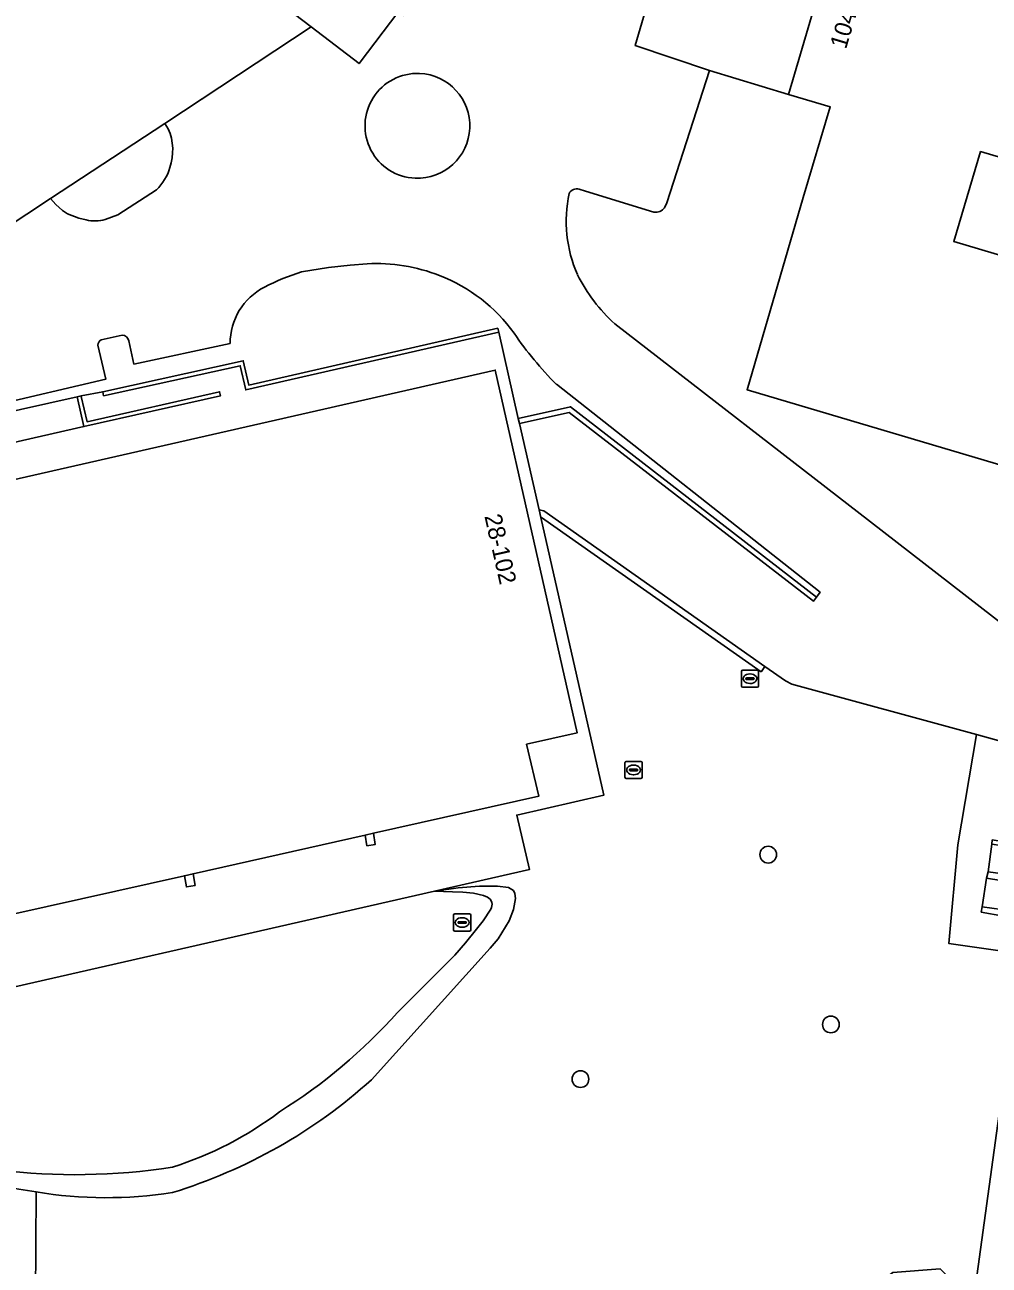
# Model space of a CAD drawing. Extents: x 161139 to 161601, y 381708 to 382245.
# Drawn here: x 161352.2 to 161408.5, y 381790 to 381862.4 of the extents above; entities that cross this region are included whole.
import ezdxf

# ---------------------------------------------------------------- set-up
doc = ezdxf.new("R2010")
doc.units = 0
for name, color, linetype in [('IMGEO_Boom', 7, 'Continuous'), ('IMGEO_Erf', 7, 'Continuous'), ('IMGEO_Groenvoorziening', 7, 'Continuous'), ('IMGEO_Hek', 7, 'Continuous'), ('IMGEO_Kolk', 7, 'Continuous'), ('IMGEO_Meer_plas_ven_vijver', 7, 'Continuous'), ('IMGEO_Muur', 7, 'Continuous'), ('IMGEO_Oever', 7, 'Continuous'), ('IMGEO_Pand', 7, 'Continuous'), ('IMGEO_Pand_nummerreeks', 7, 'Continuous'), ('IMGEO_Rijbaan_lokaal_open', 7, 'Continuous'), ('IMGEO_Rioolput', 7, 'Continuous'), ('IMGEO_Terreindeel_open', 7, 'Continuous'), ('IMGEO_Voetpad_gesloten', 7, 'Continuous'), ('IMGEO_Voetpad_op_trap', 7, 'Continuous'), ('IMGEO_Voetpad_open', 7, 'Continuous')]:
    doc.layers.add(name, color=color, linetype=linetype)

msp = doc.modelspace()

# ---------------------------------------------------------------- linework, layer by layer
at = {"layer": 'IMGEO_Boom'}
for centre in [(161395.64, 381813.956), (161399.298, 381804.049), (161384.68, 381800.857)]:
    msp.add_circle(centre, 0.489, dxfattribs=at)
at = {"layer": 'IMGEO_Erf'}
msp.add_lwpolyline([(161414.917, 381852.938), (161408.039, 381854.979), (161406.469, 381849.737), (161413.344, 381847.686)], close=True, dxfattribs=at)
at = {"layer": 'IMGEO_Groenvoorziening'}
for points in [[(161425.633, 381884.432), (161423.964, 381885.944), (161411.648, 381895.891), (161396.286, 381876.416), (161398.229, 381877.051), (161404.489, 381875.181), (161404.584, 381875.499), (161407.805, 381886.188), (161423.433, 381881.545), (161420.059, 381870.284), (161418.513, 381865.051), (161414.917, 381852.938), (161413.344, 381847.686), (161410.014, 381836.444), (161394.402, 381841.083), (161397.689, 381852.301)], [(161386.683, 381844.924), (161401.607, 381833.38), (161412.69, 381824.806), (161412.791, 381825.538), (161413.572, 381829.44), (161414.563, 381833.406), (161415.08, 381835.254), (161418.761, 381848.098), (161423.407, 381863.627), (161427.931, 381878.454)], [(161397.689, 381852.301), (161399.261, 381857.59), (161396.815, 381858.319), (161392.214, 381859.719), (161389.721, 381851.996), (161389.585, 381851.709)], [(161360.621, 381856.311), (161360.411, 381856.63), (161353.743, 381852.245), (161354.063, 381851.891), (161354.446, 381851.539), (161354.733, 381851.345), (161355.394, 381851.106), (161355.831, 381851.002)], [(161356.943, 381851.025), (161357.679, 381851.295), (161359.926, 381852.758)], [(161388.968, 381851.452), (161384.984, 381852.674), (161384.605, 381852.799)], [(161372.222, 381848.435), (161371.243, 381848.361), (161369.966, 381848.223), (161368.405, 381847.968)], [(161335.133, 381818.678), (161332.909, 381828.491), (161331.707, 381833.726), (161350.437, 381838.001), (161350.1, 381839.503), (161350.325, 381839.554), (161355.298, 381840.668), (161355.532, 381840.722), (161356.795, 381840.965), (161365.001, 381842.775), (161365.321, 381841.358), (161379.855, 381844.678), (161379.908, 381844.444), (161381.05, 381839.415), (161384.098, 381840.089), (161398.457, 381828.977), (161398.664, 381829.267), (161383.28, 381841.401)], [(161357.923, 381844.272), (161356.707, 381843.999)], [(161364.233, 381843.777), (161358.619, 381842.581), (161358.322, 381843.944)], [(161356.517, 381843.681), (161356.981, 381841.703), (161350.317, 381840.141), (161350.04, 381840.078), (161349.286, 381843.739)], [(161410.408, 381808.171), (161406.189, 381808.766), (161406.705, 381814.537), (161407.802, 381820.973), (161397.014, 381823.913), (161396.647, 381824.098), (161395.435, 381824.931), (161395.242, 381824.651), (161395.226, 381824.628), (161382.405, 381833.633), (161382.364, 381833.625), (161386.044, 381817.417), (161380.963, 381816.263), (161381.7, 381813.086), (161376.161, 381811.825), (161377.551, 381812.02), (161378.796, 381812.12), (161379.845, 381812.117), (161380.477, 381812.037), (161380.763, 381811.871), (161380.856, 381811.693), (161380.886, 381811.397), (161380.763, 381810.757), (161380.51, 381810.087), (161379.868, 381809.041), (161379.417, 381808.492), (161372.483, 381800.819)], [(161352.902, 381794.275), (161352.825, 381781.983), (161357.945, 381781.864), (161362.808, 381780.906), (161365.105, 381780.107), (161367.857, 381779.085), (161370.556, 381777.81), (161377.164, 381776.424), (161379.728, 381774.456), (161382.618, 381773.534), (161385.797, 381774.301), (161388.15, 381776.267), (161392.662, 381781.141), (161395.111, 381783.456), (161399.179, 381786.753), (161402.921, 381789.58), (161405.67, 381789.788), (161407.613, 381787.806), (161410.408, 381808.171)], [(161352.902, 381794.275), (161351.892, 381794.443), (161351.035, 381794.598), (161350.384, 381782.823), (161348.989, 381781.041), (161340.831, 381779.23), (161332.916, 381777.135), (161331.862, 381776.416), (161333.447, 381775.88), (161346.726, 381771.17)], [(161352.825, 381781.983), (161352.902, 381794.275)]]:
    msp.add_lwpolyline(points, dxfattribs=at)
msp.add_lwpolyline([(161411.998, 381819.791), (161407.802, 381820.973), (161406.705, 381814.537), (161406.189, 381808.766), (161410.408, 381808.171), (161410.678, 381810.137), (161408.076, 381810.606), (161408.129, 381810.903), (161408.388, 381812.589), (161408.472, 381812.962), (161408.693, 381814.567), (161408.72, 381814.815), (161411.254, 381814.406)], close=True, dxfattribs=at)
for centre, radius, start, end in [((161375.162, 381856.484), 3.059, 87.58326, 267.60119), ((161375.162, 381856.484), 3.059, 267.60197, 87.58247), ((161357.721, 381855.058), 3.159, 341.44108, 23.37512), ((161357.929, 381854.865), 2.904, 313.4615, 343.72954), ((161384.495, 381852.257), 0.553, 78.58059, 149.68807), ((161391.713, 381850.93), 7.861, 168.20877, 203.46151), ((161389.082, 381852.047), 0.606, 259.16034, 326.0662), ((161356.348, 381852.92), 1.986, 254.92393, 287.44588), ((161372.754, 381838.294), 10.155, 68.61842, 93.00158), ((161372.521, 381834.897), 13.704, 107.47696, 117.32043), ((161372.963, 381838.739), 9.665, 35.73286, 68.81125), ((161393.728, 381852.531), 10.368, 207.15062, 227.19873), ((161367.924, 381843.792), 3.691, 117.29862, 180.23837), ((161356.841, 381843.703), 0.325, 114.34721, 183.93748), ((161357.907, 381843.846), 0.426, 13.29849, 87.85734), ((161397.881, 381856.02), 20.662, 214.27938, 225.03631), ((161351.855, 381823.701), 30.808, 287.00415, 312.03533), ((161356.991, 381818.761), 24.825, 260.51996, 278.97631)]:
    msp.add_arc(centre, radius, start, end, dxfattribs=at)
at = {"layer": 'IMGEO_Hek'}
msp.add_lwpolyline([(161360.471, 381856.669), (161368.964, 381862.254)], dxfattribs=at)
at = {"layer": 'IMGEO_Kolk'}
for p, q in [((161377.275, 381809.571), (161377.275, 381810.423)), ((161377.35, 381810.497), (161378.202, 381810.497)), ((161377.534, 381809.991), (161377.534, 381810.003)), ((161377.972, 381809.954), (161377.574, 381809.954)), ((161377.577, 381810.04), (161377.975, 381810.04)), ((161377.763, 381810.277), (161377.788, 381810.277)), ((161378.018, 381810.003), (161378.018, 381809.991)), ((161378.276, 381810.423), (161378.276, 381809.571)), ((161378.202, 381809.497), (161377.35, 381809.497)), ((161377.786, 381809.717), (161377.761, 381809.717))]:
    msp.add_line(p, q, dxfattribs=at)
for points in [[(161377.275, 381809.571), (161377.275, 381810.423)], [(161377.35, 381810.497), (161378.202, 381810.497)], [(161378.276, 381810.423), (161378.276, 381809.571)], [(161378.202, 381809.497), (161377.35, 381809.497)]]:
    msp.add_lwpolyline(points, dxfattribs=at)
for centre, radius, start, end in [((161377.352, 381810.421), 0.0765, 91.55205, 178.44795), ((161377.352, 381810.421), 0.0765, 91.55205, 178.44795), ((161377.574, 381810), 0.0403, 85.87752, 175.75265), ((161377.571, 381809.99), 0.0366, 178.93798, 274.71019), ((161377.975, 381809.997), 0.043, 264.86636, 352.45326), ((161377.979, 381810.002), 0.0386, 1.73085, 96.63898), ((161378.2, 381810.421), 0.0765, 1.55205, 88.44795), ((161378.2, 381810.421), 0.0765, 1.55205, 88.44795), ((161377.352, 381809.573), 0.0765, 181.55205, 268.44795), ((161377.352, 381809.573), 0.0765, 181.55205, 268.44795), ((161378.2, 381809.573), 0.0765, 271.55205, 358.44795), ((161378.2, 381809.573), 0.0765, 271.55205, 358.44795)]:
    msp.add_arc(centre, radius, start, end, dxfattribs=at)
for centre, major_axis, ratio, start_param, end_param in [((161377.762, 381809.997), (-0.387, 0.002), 0.722429, 4.712389, 7.853982), ((161377.787, 381809.997), (-0.39, 0.002), 0.717154, 1.570796, 4.712389)]:
    msp.add_ellipse(centre, major_axis=major_axis, ratio=ratio, start_param=start_param, end_param=end_param, dxfattribs=at)
at = {"layer": 'IMGEO_Meer_plas_ven_vijver'}
for points in [[(161379.253, 381811.478), (161379.022, 381811.576), (161378.438, 381811.701), (161377.818, 381811.759), (161377.209, 381811.777), (161376.161, 381811.825), (161343.697, 381804.435), (161342.975, 381807.593), (161337.913, 381806.476), (161335.626, 381816.503), (161335.311, 381817.891), (161333.874, 381818.717), (161332.482, 381819.2), (161331.351, 381819.078), (161330.206, 381818.17), (161329.421, 381816.748)], [(161374.01, 381804.748), (161377.35, 381808.099), (161377.97, 381808.813), (161378.62, 381809.605), (161379.002, 381810.101), (161379.441, 381810.778)]]:
    msp.add_lwpolyline(points, dxfattribs=at)
for centre, radius, start, end in [((161379.034, 381811.044), 0.486, 326.8708, 63.19572), ((161349.812, 381826.516), 32.548, 302.10862, 318.02666), ((161354.673, 381815.366), 20.6, 287.49309, 307.14576), ((161355.18, 381832.325), 37.045, 247.27121, 278.82728)]:
    msp.add_arc(centre, radius, start, end, dxfattribs=at)
at = {"layer": 'IMGEO_Muur'}
for points in [[(161365.001, 381842.775), (161356.795, 381840.965), (161356.848, 381840.731), (161364.82, 381842.488), (161365.139, 381841.071), (161379.908, 381844.444), (161379.855, 381844.678), (161365.321, 381841.358)], [(161363.671, 381840.733), (161363.619, 381840.967), (161355.876, 381839.221), (161355.539, 381840.688), (161355.532, 381840.722), (161355.298, 381840.668), (161355.696, 381838.933)], [(161384.098, 381840.089), (161381.05, 381839.415), (161381.116, 381839.122), (161384.026, 381839.765), (161398.283, 381828.747), (161398.457, 381828.977)], [(161382.536, 381834.012), (161382.262, 381834.074), (161382.364, 381833.625), (161382.405, 381833.633), (161395.226, 381824.628), (161395.242, 381824.651), (161395.435, 381824.931)], [(161372.602, 381815.202), (161372.116, 381815.093), (161372.212, 381814.475), (161372.702, 381814.55)], [(161362.067, 381812.837), (161361.567, 381812.725), (161361.679, 381812.074), (161362.182, 381812.161)]]:
    msp.add_lwpolyline(points, close=True, dxfattribs=at)
at = {"layer": 'IMGEO_Oever'}
for points in [[(161379.417, 381808.492), (161379.868, 381809.041), (161380.51, 381810.087), (161380.763, 381810.757), (161380.886, 381811.397), (161380.856, 381811.693), (161380.763, 381811.871), (161380.477, 381812.037), (161379.845, 381812.117), (161378.796, 381812.12), (161377.551, 381812.02), (161376.161, 381811.825), (161377.209, 381811.777), (161377.818, 381811.759), (161378.438, 381811.701), (161379.022, 381811.576), (161379.253, 381811.478)], [(161379.441, 381810.778), (161379.002, 381810.101), (161378.62, 381809.605), (161377.97, 381808.813), (161377.35, 381808.099), (161374.01, 381804.748)], [(161372.483, 381800.819), (161379.417, 381808.492)], [(161351.035, 381794.598), (161351.892, 381794.443), (161352.902, 381794.275)]]:
    msp.add_lwpolyline(points, dxfattribs=at)
for centre, radius, start, end in [((161379.034, 381811.044), 0.486, 326.8708, 63.19572), ((161349.812, 381826.516), 32.548, 302.10862, 318.02666), ((161351.855, 381823.701), 30.808, 287.00415, 312.03533), ((161354.673, 381815.366), 20.6, 287.49309, 307.14576), ((161355.18, 381832.325), 37.045, 247.27121, 278.82728), ((161356.991, 381818.761), 24.825, 260.51996, 278.97631)]:
    msp.add_arc(centre, radius, start, end, dxfattribs=at)
at = {"layer": 'IMGEO_Pand'}
for points in [[(161390.838, 381885.171), (161376.851, 381895.819), (161375.084, 381893.489), (161373.955, 381892.001), (161370.262, 381894.819), (161369.955, 381894.435), (161364, 381886.63), (161365.51, 381885.478), (161362.5, 381881.493), (161362.266, 381881.673), (161355.333, 381872.637), (161355.437, 381872.558), (161368.964, 381862.254), (161371.759, 381860.122), (161374.079, 381863.168), (161378.602, 381869.107), (161378.802, 381869.369), (161381.677, 381873.144)], [(161418.513, 381865.051), (161411.633, 381867.094), (161413.178, 381872.321), (161413.216, 381872.31), (161420.059, 381870.284), (161423.433, 381881.545), (161407.805, 381886.188), (161404.584, 381875.499), (161404.489, 381875.181), (161404.449, 381875.049), (161404.403, 381874.894), (161402.871, 381869.734), (161400.411, 381870.476), (161400.337, 381870.225), (161399.821, 381868.48), (161396.815, 381858.319), (161399.261, 381857.59), (161397.689, 381852.301), (161394.402, 381841.083), (161410.014, 381836.444), (161413.344, 381847.686), (161406.469, 381849.737), (161408.039, 381854.979), (161414.917, 381852.938)], [(161355.437, 381872.558), (161351.666, 381870.071), (161351.507, 381870.313), (161342.013, 381864.045), (161337.847, 381861.294), (161342.849, 381853.685), (161345.758, 381855.638), (161346.996, 381856.469), (161350.973, 381850.423), (161353.743, 381852.245), (161360.411, 381856.63), (161368.964, 381862.254)], [(161379.704, 381842.234), (161335.829, 381832.246), (161336.494, 381829.305), (161333.143, 381828.544), (161332.909, 381828.491), (161335.133, 381818.678), (161335.311, 381817.891), (161335.626, 381816.503), (161336.314, 381816.639), (161337.709, 381810.412), (161340.665, 381811.043), (161341.308, 381808.177), (161351.034, 381810.36), (161351.547, 381810.476), (161361.567, 381812.725), (161362.067, 381812.837), (161372.116, 381815.093), (161372.602, 381815.202), (161382.243, 381817.366), (161381.533, 381820.401), (161384.492, 381821.071)]]:
    msp.add_lwpolyline(points, close=True, dxfattribs=at)
at = {"layer": 'IMGEO_Rijbaan_lokaal_open'}
for points in [[(161389.585, 381851.709), (161389.721, 381851.996), (161392.214, 381859.719), (161387.882, 381861.165), (161389.294, 381866.012), (161390.047, 381867.09), (161389.223, 381867.644), (161389.02, 381867.798), (161388.983, 381867.825), (161384.784, 381871), (161384.544, 381871.18), (161385.946, 381873.035), (161396.286, 381876.416), (161411.648, 381895.891)], [(161374.394, 381862.928), (161374.079, 381863.168), (161371.759, 381860.122), (161368.964, 381862.254), (161360.411, 381856.63), (161360.621, 381856.311)], [(161355.831, 381851.002), (161355.394, 381851.106), (161354.733, 381851.345), (161354.446, 381851.539), (161354.063, 381851.891), (161353.743, 381852.245), (161350.973, 381850.423), (161346.996, 381856.469), (161345.758, 381855.638), (161347.059, 381853.701)], [(161359.926, 381852.758), (161357.679, 381851.295), (161356.943, 381851.025)], [(161384.605, 381852.799), (161384.984, 381852.674), (161388.968, 381851.452)], [(161368.405, 381847.968), (161369.966, 381848.223), (161371.243, 381848.361), (161372.222, 381848.435)], [(161383.28, 381841.401), (161398.664, 381829.267), (161398.457, 381828.977), (161398.283, 381828.747), (161384.026, 381839.765), (161381.116, 381839.122), (161382.262, 381834.074), (161382.536, 381834.012), (161395.435, 381824.931), (161396.647, 381824.098), (161397.014, 381823.913), (161407.802, 381820.973), (161411.998, 381819.791), (161412.69, 381824.806), (161401.607, 381833.38), (161386.683, 381844.924)], [(161356.707, 381843.999), (161357.923, 381844.272)], [(161358.322, 381843.944), (161358.619, 381842.581), (161364.233, 381843.777)], [(161349.286, 381843.739), (161350.04, 381840.078), (161350.317, 381840.141), (161356.981, 381841.703), (161356.517, 381843.681)]]:
    msp.add_lwpolyline(points, dxfattribs=at)
for centre, radius, start, end in [((161375.162, 381856.484), 3.059, 87.58326, 267.60119), ((161375.162, 381856.484), 3.059, 267.60197, 87.58247), ((161357.721, 381855.058), 3.159, 341.44108, 23.37512), ((161357.929, 381854.865), 2.904, 313.4615, 343.72954), ((161384.495, 381852.257), 0.553, 78.58059, 149.68807), ((161391.713, 381850.93), 7.861, 168.20877, 203.46151), ((161389.082, 381852.047), 0.606, 259.16034, 326.0662), ((161356.348, 381852.92), 1.986, 254.92393, 287.44588), ((161372.754, 381838.294), 10.155, 68.61842, 93.00158), ((161372.521, 381834.897), 13.704, 107.47696, 117.32043), ((161372.963, 381838.739), 9.665, 35.73286, 68.81125), ((161393.728, 381852.531), 10.368, 207.15062, 227.19873), ((161367.924, 381843.792), 3.691, 117.29862, 180.23837), ((161356.841, 381843.703), 0.325, 114.34721, 183.93748), ((161357.907, 381843.846), 0.426, 13.29849, 87.85734), ((161397.881, 381856.02), 20.662, 214.27938, 225.03631)]:
    msp.add_arc(centre, radius, start, end, dxfattribs=at)
at = {"layer": 'IMGEO_Rioolput'}
for p, q in [((161394.077, 381823.796), (161394.077, 381824.648)), ((161394.152, 381824.722), (161395.004, 381824.722)), ((161394.565, 381824.502), (161394.59, 381824.502)), ((161395.078, 381824.648), (161395.078, 381823.796)), ((161395.004, 381823.722), (161394.152, 381823.722)), ((161394.336, 381824.216), (161394.336, 381824.228)), ((161394.774, 381824.179), (161394.376, 381824.179)), ((161394.379, 381824.265), (161394.777, 381824.265)), ((161394.588, 381823.942), (161394.563, 381823.942)), ((161394.82, 381824.228), (161394.82, 381824.216)), ((161387.278, 381818.472), (161387.278, 381819.324)), ((161387.353, 381819.398), (161388.205, 381819.398)), ((161388.279, 381819.324), (161388.279, 381818.472)), ((161387.537, 381818.892), (161387.537, 381818.904)), ((161387.975, 381818.855), (161387.577, 381818.855)), ((161387.58, 381818.941), (161387.978, 381818.941)), ((161387.789, 381818.618), (161387.764, 381818.618)), ((161387.766, 381819.178), (161387.791, 381819.178)), ((161388.021, 381818.904), (161388.021, 381818.892)), ((161388.205, 381818.398), (161387.353, 381818.398))]:
    msp.add_line(p, q, dxfattribs=at)
for points in [[(161394.077, 381823.796), (161394.077, 381824.648)], [(161394.152, 381824.722), (161395.004, 381824.722)], [(161395.078, 381824.648), (161395.078, 381823.796)], [(161395.004, 381823.722), (161394.152, 381823.722)], [(161387.278, 381818.472), (161387.278, 381819.324)], [(161387.353, 381819.398), (161388.205, 381819.398)], [(161388.279, 381819.324), (161388.279, 381818.472)], [(161388.205, 381818.398), (161387.353, 381818.398)]]:
    msp.add_lwpolyline(points, dxfattribs=at)
for centre, radius, start, end in [((161394.154, 381824.646), 0.0765, 91.55205, 178.44795), ((161394.154, 381824.646), 0.0765, 91.55205, 178.44795), ((161395.002, 381824.646), 0.0765, 1.55205, 88.44795), ((161395.002, 381824.646), 0.0765, 1.55205, 88.44795), ((161394.154, 381823.798), 0.0765, 181.55205, 268.44795), ((161394.154, 381823.798), 0.0765, 181.55205, 268.44795), ((161394.376, 381824.225), 0.0403, 85.87752, 175.75265), ((161394.373, 381824.215), 0.0366, 178.93798, 274.71019), ((161394.777, 381824.222), 0.043, 264.86636, 352.45326), ((161394.781, 381824.227), 0.0386, 1.73085, 96.63898), ((161395.002, 381823.798), 0.0765, 271.55205, 358.44795), ((161395.002, 381823.798), 0.0765, 271.55205, 358.44795), ((161387.355, 381819.322), 0.0765, 91.55205, 178.44795), ((161387.355, 381819.322), 0.0765, 91.55205, 178.44795), ((161388.203, 381819.322), 0.0765, 1.55205, 88.44795), ((161388.203, 381819.322), 0.0765, 1.55205, 88.44795), ((161387.577, 381818.901), 0.0403, 85.87752, 175.75265), ((161387.574, 381818.891), 0.0366, 178.93798, 274.71019), ((161387.978, 381818.898), 0.043, 264.86636, 352.45326), ((161387.982, 381818.903), 0.0386, 1.73085, 96.63898), ((161387.355, 381818.474), 0.0765, 181.55205, 268.44795), ((161387.355, 381818.474), 0.0765, 181.55205, 268.44795), ((161388.203, 381818.474), 0.0765, 271.55205, 358.44795), ((161388.203, 381818.474), 0.0765, 271.55205, 358.44795)]:
    msp.add_arc(centre, radius, start, end, dxfattribs=at)
for centre, major_axis, ratio, start_param, end_param in [((161394.564, 381824.222), (-0.387, 0.002), 0.722429, 4.712389, 7.853982), ((161394.589, 381824.222), (-0.39, 0.002), 0.717154, 1.570796, 4.712389), ((161387.765, 381818.898), (-0.387, 0.002), 0.722429, 4.712389, 7.853982), ((161387.79, 381818.898), (-0.39, 0.002), 0.717154, 1.570796, 4.712389)]:
    msp.add_ellipse(centre, major_axis=major_axis, ratio=ratio, start_param=start_param, end_param=end_param, dxfattribs=at)
at = {"layer": 'IMGEO_Terreindeel_open'}
for points in [[(161343.697, 381804.435), (161376.161, 381811.825), (161381.7, 381813.086), (161380.963, 381816.263), (161386.044, 381817.417), (161382.364, 381833.625), (161382.262, 381834.074), (161381.116, 381839.122), (161381.05, 381839.415), (161379.908, 381844.444), (161365.139, 381841.071), (161364.82, 381842.488), (161356.848, 381840.731), (161356.795, 381840.965), (161355.532, 381840.722), (161355.539, 381840.688), (161355.876, 381839.221), (161363.619, 381840.967), (161363.671, 381840.733), (161355.696, 381838.933), (161350.722, 381837.807)], [(161335.829, 381832.246), (161379.704, 381842.234), (161384.492, 381821.071), (161381.533, 381820.401), (161382.243, 381817.366), (161372.602, 381815.202), (161372.702, 381814.55), (161372.212, 381814.475), (161372.116, 381815.093), (161362.067, 381812.837), (161362.182, 381812.161), (161361.679, 381812.074), (161361.567, 381812.725), (161351.547, 381810.476)]]:
    msp.add_lwpolyline(points, dxfattribs=at)
at = {"layer": 'IMGEO_Voetpad_gesloten'}
for points in [[(161399.821, 381868.48), (161398.279, 381868.954), (161396.671, 381863.647), (161391.264, 381865.226), (161391.555, 381865.65), (161396.198, 381866.981), (161395.311, 381869.871), (161390.886, 381868.403), (161389.475, 381867.942), (161389.223, 381867.644), (161390.047, 381867.09), (161389.294, 381866.012), (161387.882, 381861.165), (161392.214, 381859.719), (161396.815, 381858.319)], [(161410.276, 381814.337), (161408.693, 381814.567), (161408.472, 381812.962), (161410.042, 381812.734)], [(161410.05, 381812.318), (161408.388, 381812.589), (161408.129, 381810.903), (161409.815, 381810.668)]]:
    msp.add_lwpolyline(points, close=True, dxfattribs=at)
at = {"layer": 'IMGEO_Voetpad_op_trap'}
msp.add_lwpolyline([(161355.298, 381840.668), (161350.325, 381839.554), (161350.722, 381837.807), (161355.696, 381838.933)], close=True, dxfattribs=at)
at = {"layer": 'IMGEO_Voetpad_open'}
for points in [[(161410.042, 381812.734), (161408.472, 381812.962), (161408.388, 381812.589), (161410.05, 381812.318)], [(161409.815, 381810.668), (161408.129, 381810.903), (161408.076, 381810.606), (161410.678, 381810.137)], [(161410.408, 381808.171), (161407.613, 381787.806), (161406.912, 381782.697), (161404.234, 381763.186)]]:
    msp.add_lwpolyline(points, dxfattribs=at)

# ---------------------------------------------------------------- texts
at = {"layer": 'IMGEO_Pand_nummerreeks'}
for s, rotation, p in [('104-118', 73.32141, (161400.178, 381860.917)), ('28-102', 282.7481, (161379.068, 381833.714))]:
    msp.add_text(s, height=1, rotation=rotation, dxfattribs=at).set_placement(p)

doc.saveas('drawing.dxf')
